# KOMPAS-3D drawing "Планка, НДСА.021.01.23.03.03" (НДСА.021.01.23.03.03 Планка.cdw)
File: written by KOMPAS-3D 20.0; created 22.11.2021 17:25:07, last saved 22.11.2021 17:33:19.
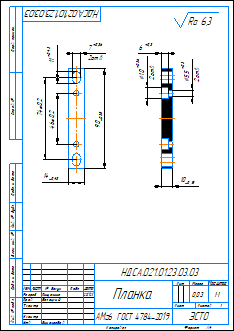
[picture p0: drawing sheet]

Sheet 1: A4, portrait

Document properties: Параметр неуказанной шероховатости: Ra 6,3; PLM_CDWXDTO: <item xmlns="http://appius.ru/pdm" xmlns:xs="http://www.w3.org/2001/XMLSchema" xmlns:xsi="http://www.w3.org/2001/XMLSchema-instance" xsi:type="item">  <element xmlns:d2p1="http://v8.1c.ru/8.1/data/enterprise/current-config" xsi:type="d2p1:CatalogRef.aps_Элемен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; PDM_DOCXDTO: <item xmlns="http://appius.ru/pdm" xmlns:xs="http://www.w3.org/2001/XMLSchema" xmlns:xsi="http://www.w3.org/2001/XMLSchema-instance" xsi:type="item">  <element xmlns:d2p1="http://v8.1c.ru/8.1/data/enterprise/current-config" xsi:type="d2p1:CatalogRef.aps_Элемен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; PDM_ITEMXDTO: <item xmlns="http://appius.ru/pdm" xmlns:xs="http://www.w3.org/2001/XMLSchema" xmlns:xsi="http://www.w3.org/2001/XMLSchema-instance" xsi:type="item">  <element xmlns:d2p1="http://v8.1c.ru/8.1/data/enterprise/current-config" xsi:type="d2p1:CatalogRef.aps_Элемен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; Масса: 0.0267637

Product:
- Part/product: Планка  | designation НДСА.021.01.23.03.03
    Материал: АМг6  ГОСТ 4784-2019 (density 2640 kg/m3)
    Масса: 0.0267637
    additional columns: <item xmlns="http://appius.ru/pdm" xmlns:xs="http://www.w3.org/2001/XMLSchema" x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; <item xmlns="http://appius.ru/pdm" xmlns:xs="http://www.w3.org/2001/XMLSchema" x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
    source file: НДСА.021.01.23.03.03 Планка.cdw

Title block, sheet 1: Наименование: Планка; designation: НДСА.021.01.23.03.03; Материал: АМг6  ГОСТ 4784-2019; Масса: 0,03; Количество листов документа: 1; organisation: ЭСТО; Форматы листов документа: A4; stored path: C:\Users\s.pischagina\Desktop\PLM\НДСА.021.01.23.03.03 Планка.cdw; Разработал: Пищагина; Проверил: Белецкий; Утвердил: Виноградов; Разработал, date: 22.11.21

Views: Вид 1, Сверху, Проекционный вид 2, Местный разрез 1
Referenced files in C:\Users\s.pischagina\Desktop\PLM\: НДСА.021.01.23.03.03 Планка.m3d
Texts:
  Ra 6,3
  НДСА.021.01.23.03.03 Планка
Dimensions and other numbers on the sheet: 46±0,2; 74±0,2; 90; 11; 7; 2отв; 14; 10; 6; 5,5; 1:1; 1; 0,03; 22.11.21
